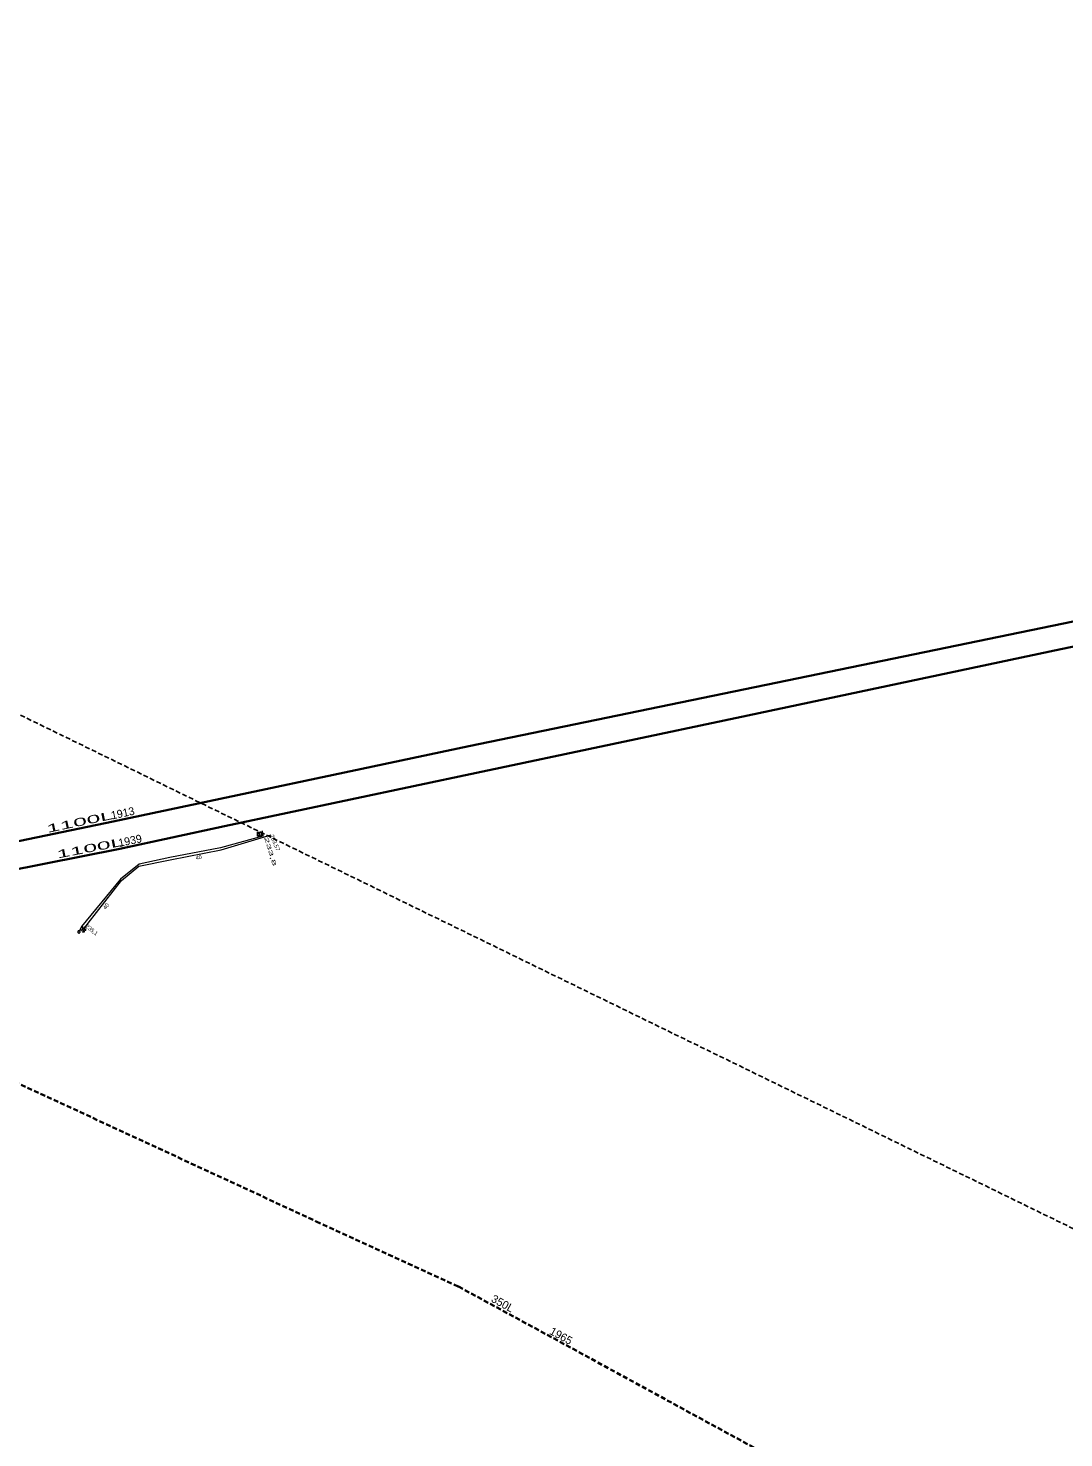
# Model space of a CAD drawing. Extents: x -735085 to -733500, y -1044153 to -1043402.
# Drawn here: x -734101.4 to -733894.4, y -1043978.5 to -1043696.6 of the extents above; entities that cross this region are included whole.
import ezdxf

# ---------------------------------------------------------------- set-up
doc = ezdxf.new("R2010")
doc.units = 0
doc.header["$LTSCALE"] = 0.32
doc.linetypes.add('MEDIUM_DASHED', pattern=[4.5, 3, -1.5])
doc.layers.add('15', color=7, linetype='Continuous')
doc.layers.add('16', color=7, linetype='Continuous')
for name, color, linetype, lineweight in [('18', 7, 'Continuous', 13), ('50', 7, 'Continuous', 13), ('63', 7, 'MEDIUM_DASHED', 25), ('8', 7, 'Continuous', 13)]:
    doc.layers.add(name, color=color, linetype=linetype, lineweight=lineweight)

msp = doc.modelspace()

# ---------------------------------------------------------------- linework, layer by layer
at = {"layer": '18'}
for points in [[(-734090.848, -1043876.709), (-734090.853, -1043876.786), (-734090.848, -1043876.863), (-734090.831, -1043876.938), (-734090.803, -1043877.009), (-734090.762, -1043877.075), (-734090.747, -1043877.097)], [(-734090.503, -1043876.317), (-734090.574, -1043876.345), (-734090.641, -1043876.384), (-734090.701, -1043876.432), (-734090.752, -1043876.489), (-734090.776, -1043876.523)], [(-734090.59, -1043877.226), (-734090.52, -1043877.257), (-734090.445, -1043877.276), (-734090.369, -1043877.283), (-734090.292, -1043877.278), (-734090.217, -1043877.261), (-734090.145, -1043877.233), (-734090.085, -1043877.198)], [(-734089.962, -1043876.5), (-734090.012, -1043876.442), (-734090.07, -1043876.392), (-734090.135, -1043876.351), (-734090.206, -1043876.322), (-734090.255, -1043876.308)], [(-734089.967, -1043877.086), (-734089.926, -1043877.021), (-734089.895, -1043876.951), (-734089.875, -1043876.876), (-734089.868, -1043876.8), (-734089.873, -1043876.723), (-734089.879, -1043876.688)]]:
    msp.add_lwpolyline(points, dxfattribs=at)
msp.add_lwpolyline([(-734090.119, -1043876.769), (-734090.125, -1043876.717), (-734090.142, -1043876.667), (-734090.171, -1043876.623), (-734090.209, -1043876.586), (-734090.254, -1043876.559), (-734090.304, -1043876.543), (-734090.356, -1043876.538), (-734090.407, -1043876.545), (-734090.456, -1043876.564), (-734090.5, -1043876.594), (-734090.536, -1043876.633), (-734090.562, -1043876.678), (-734090.576, -1043876.729), (-734090.58, -1043876.781), (-734090.571, -1043876.833), (-734090.551, -1043876.881), (-734090.521, -1043876.924), (-734090.481, -1043876.959), (-734090.434, -1043876.983), (-734090.384, -1043876.997), (-734090.331, -1043876.999), (-734090.28, -1043876.989), (-734090.232, -1043876.967), (-734090.19, -1043876.935), (-734090.157, -1043876.895), (-734090.133, -1043876.848), (-734090.12, -1043876.797)], close=True, dxfattribs=at)
at = {"layer": '50'}
msp.add_lwpolyline([(-734090.35, -1043876.78), (-734089.41, -1043875.57), (-734082.77, -1043867.01), (-734079.27, -1043864.15), (-734073.03, -1043862.84), (-734062.85, -1043860.87), (-734052.82, -1043857.88)], dxfattribs=at)
msp.add_lwpolyline([(-734090.35, -1043876.78), (-734089.41, -1043875.57), (-734082.77, -1043867.01), (-734079.27, -1043864.15), (-734073.03, -1043862.84), (-734062.85, -1043860.87), (-734052.82, -1043857.88)], dxfattribs=at)
at = {"layer": '63'}
msp.add_lwpolyline([(-734957.565, -1043435.501), (-734250.468, -1043761.931), (-734250.468, -1043761.931), (-733815.986, -1043973.969)], dxfattribs=at)
at = {"layer": '8', "lineweight": 35}
for points in [[(-733500.14, -1043736.5), (-733578.17, -1043751.88), (-733749.774, -1043785.92), (-733782.129, -1043791.12), (-733828.849, -1043802.13), (-733843.715, -1043805.114), (-734013.309, -1043840.11), (-734084.403, -1043855.21), (-734114.903, -1043861.54), (-734140.791, -1043867.289)], [(-733499.8, -1043741.34), (-733577.602, -1043756.92), (-733749.741, -1043791.62), (-733780.166, -1043797.47), (-733830.039, -1043807.22), (-733842.373, -1043809.844), (-733894.938, -1043820.77), (-733957.55, -1043834.01), (-734011.796, -1043845.47), (-734062.127, -1043856.17), (-734083.072, -1043860.7), (-734113.399, -1043866.69), (-734129.342, -1043869.95), (-734133.254, -1043870.63)]]:
    msp.add_lwpolyline(points, dxfattribs=at)
at = {"layer": '8'}
for points in [[(-734054.609, -1043857.09), (-734054.5, -1043858.12), (-734062.98, -1043860.47), (-734073.079, -1043862.4), (-734079.239, -1043863.71), (-734082.969, -1043866.71), (-734090.77, -1043876.19), (-734091.27, -1043877.29)], [(-734055.356, -1043857.947), (-734055.346, -1043857.99), (-734055.324, -1043858.029), (-734055.293, -1043858.06), (-734055.255, -1043858.081), (-734055.212, -1043858.092), (-734055.168, -1043858.09), (-734055.126, -1043858.077), (-734055.089, -1043858.053), (-734055.06, -1043858.02), (-734055.041, -1043857.98), (-734055.033, -1043857.937), (-734055.037, -1043857.893), (-734055.053, -1043857.852), (-734055.079, -1043857.817), (-734055.114, -1043857.79), (-734055.155, -1043857.773), (-734055.181, -1043857.768)], [(-734055.034, -1043857.61), (-734055.039, -1043857.567), (-734055.056, -1043857.526), (-734055.083, -1043857.492), (-734055.119, -1043857.466), (-734055.16, -1043857.451), (-734055.203, -1043857.448), (-734055.246, -1043857.456), (-734055.285, -1043857.476), (-734055.318, -1043857.505), (-734055.341, -1043857.543), (-734055.353, -1043857.585), (-734055.354, -1043857.628), (-734055.342, -1043857.671), (-734055.32, -1043857.708), (-734055.288, -1043857.739), (-734055.25, -1043857.759), (-734055.207, -1043857.768), (-734055.181, -1043857.768)]]:
    msp.add_lwpolyline(points, dxfattribs=at)
for points in [[(-734055.583, -1043857.364), (-734054.793, -1043857.364), (-734054.793, -1043858.164), (-734055.583, -1043858.164)], [(-734091.356, -1043877.504), (-734091.306, -1043877.52), (-734091.253, -1043877.524), (-734091.201, -1043877.517), (-734091.152, -1043877.498), (-734091.108, -1043877.468), (-734091.073, -1043877.429), (-734091.047, -1043877.384), (-734091.032, -1043877.334), (-734091.029, -1043877.281), (-734091.038, -1043877.229), (-734091.059, -1043877.181), (-734091.089, -1043877.139), (-734091.13, -1043877.104), (-734091.176, -1043877.079), (-734091.226, -1043877.065), (-734091.279, -1043877.065), (-734091.33, -1043877.074), (-734091.379, -1043877.096), (-734091.42, -1043877.128), (-734091.453, -1043877.169), (-734091.477, -1043877.215), (-734091.489, -1043877.267), (-734091.489, -1043877.319), (-734091.477, -1043877.371), (-734091.455, -1043877.417), (-734091.422, -1043877.459), (-734091.38, -1043877.491)]]:
    msp.add_lwpolyline(points, close=True, dxfattribs=at)
at = {"layer": '8', "linetype": 'MEDIUM_DASHED', "lineweight": 35}
msp.add_lwpolyline([(-734156.787, -1043882.494), (-734117.203, -1043901.187), (-734043.806, -1043935.179), (-734015.348, -1043948.221), (-733950.381, -1043983.651), (-733846.87, -1044026.74)], dxfattribs=at)

# ---------------------------------------------------------------- texts
at = {"layer": '15'}
for s, rotation, p in [('1913', 12, (-734084.669, -1043854.811)), ('1939', 12, (-734083.197, -1043860.316)), ('350L', 331, (-734009.004, -1043951.141)), ('1965', 331, (-733997.328, -1043957.619))]:
    msp.add_text(s, height=1.6, rotation=rotation, dxfattribs=at).set_placement(p)
at = {"layer": '15', "width": 2.3}
for rotation, p in [(12, (-734097.571, -1043857.493)), (11, (-734095.563, -1043862.612))]:
    msp.add_text('1100L ', height=1.6, rotation=rotation, dxfattribs=at).set_placement(p)
at = {"layer": '16', "width": 2.25}
msp.add_text('233,8 ', height=0.8, rotation=287, dxfattribs=at).set_placement((-734054.233, -1043858.42))
at = {"layer": '16'}
for s, rotation, p in [('233,57', 293, (-734053.088, -1043858.046)), ('40', 11, (-734067.852, -1043862.886)), ('40', 52, (-734085.909, -1043872.876)), ('235,1 ', 322, (-734090.024, -1043876.353))]:
    msp.add_text(s, height=0.8, rotation=rotation, dxfattribs=at).set_placement(p)

doc.saveas('drawing.dxf')
